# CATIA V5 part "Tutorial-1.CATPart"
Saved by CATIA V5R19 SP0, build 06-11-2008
Part number: c06_tut1
Bounding box of the stored display mesh (mm): x -101.839 to 0, y -66 to 66, z 0 to 106.23
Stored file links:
  D:\Shriniwas\v5_r19\Part files\c06\c06_tut1.CATPart
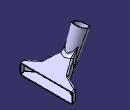
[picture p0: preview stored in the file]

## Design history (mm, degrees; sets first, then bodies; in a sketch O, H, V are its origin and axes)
Body1 (main body)
  Sketch1 on zx-plane, origin (0, 0, 0), H (-1, 0, 0), V (0, 0, 1)
    axis line L1 (0, 0) -> (178.0059, 0)
    line L2 (0, 0) -> (53.9276, 26.3023)
    line L3 (53.9276, 26.3023) -> (86.4666, 99.3859)
    point P3 (86.4666, 99.3859)
    angle L1 L2 = 26
    angle L2 L3 = 140
    length L3 = 80
    length L2 = 60
    horizontal: L1 H
  Sketch2 on yz-plane, origin (0, 0, 0), H (0, 1, 0), V (0, 0, 1)
    point P1 (79.721, 0)
    coincidence: P1 H
  Plane1 "Plane.1": type 3Points, Element1 Sketch2, Element2 Sketch1.O, Element3 vertex [element of Sketch1 | element of Sketch1]
  Sketch3 on Plane1, origin (0, 0, 0), H (0, -1, 0), V (-0.8988, 0, 0.4384)
    line L1 (0, 0) -> (-66, 0)
    point P1 (-66, 0)
    line L2 (-66, 0) -> (-65.4759, 10)
    point P2 (-65.4759, 10)
    line L3 (-65.4759, 10) -> (-33, 25)
    point P3 (-33, 25)
    line L4 (-33, 25) -> (-12.1773, 65)
    point P4 (-12.1773, 65)
    line L5 (-12.1773, 65) -> (0, 65)
    point P5 (0, 65)
    point P6 (65.4759, 10)
    point P7 (66, 0)
    line L6 (66, 0) -> (65.4759, 10)
    point P8 (33, 25)
    line L7 (65.4759, 10) -> (33, 25)
    point P9 (0, 0)
    line L8 (0, 0) -> (66, 0)
    point P10 (12.1773, 65)
    line L9 (33, 25) -> (12.1773, 65)
    point P11 (0, 65)
    line L10 (12.1773, 65) -> (0, 65)
    axis line L11 (66, 0) -> (66, 76.5877)
    angle L4 L9 = 55
    distance P3 P8 = 66
    distance P7 P1 = 132
    angle L11 L6 = 3
    distance P1 P2 V = 10
    distance L1 P3 = 25
    distance L5 L1 = 65
    horizontal: L1 H, L5 H
    coincidence: P5 V, O P9, P5 P11
    symmetry: P2 P6 V, P1 P7 V, L2 L6 V, P3 P8 V, L3 L7 V, O P9 V, L1 L8 V, P4 P10 V, L4 L9 V, P5 P11 V, L5 L10 V
    vertical: L11 V
  Pad1: profile Sketch3, direction along xy-plane, length 28
  Plane2 "Plane.2": type Normal, Curve Sketch1, RefPoint Sketch1.P3
  Sketch4 on Plane2, origin (-51.2336, 0, 115.0726), H (0, -1, 0), V (0.9135, 0, 0.4067)
    circle A1 centre (0, -38.5673) radius 17
    point P1 (0, -38.5673)
    reference projected point E1 (0, -38.5673) from Sketch1.P3
    radius A1 = 17
    coincidence: P1 E1
  Pad2: profile Sketch4, direction (0.4067, 0, -0.9135), length 0, opposite side up to Plane1
  Draft1: Angle 2, SupportToDraft face of Pad2 from Sketch4.A1, PullDir end face of Pad2, Neutral end face of Pad2
  Fillet1: radius 12, on edge [face of Pad2 from Sketch4.A1 | end face of Pad1]; edge [face of Pad2 from Sketch4.A1 | face of Pad1 from Sketch3.L4]; edge [face of Pad2 from Sketch4.A1 | face of Pad1 from Sketch3.L9]
  Fillet2: radius 3, on edge [face of Pad1 from Sketch3.L4 | end face of Pad1]; edge [end face of Pad1 | face of Pad1 from Sketch3.L3]; edge [face of Fillet1 | face of Fillet1]; edge [end face of Pad1 | face of Pad1 from Sketch3.L7]; edge [end face of Pad1 | face of Pad1 from Sketch3.L6]; edge [face of Pad1 from Sketch3.L7 | face of Pad1]; edge [end face of Pad1 | face of Pad1 from Sketch3.L2]; edge [face of Pad1 | face of Pad1 from Sketch3.L9]; edge [face of Pad1 from Sketch3.L3 | face of Pad1]; edge [face of Pad1 from Sketch3.L7 | face of Pad1 from Sketch3.L9]; edge [face of Pad1 from Sketch3.L4 | face of Pad1 from Sketch3.L3]; edge [face of Pad1 from Sketch3.L6 | face of Pad1]; edge [face of Pad1 from Sketch3.L6 | face of Pad1 from Sketch3.L7]; edge [face of Pad1 from Sketch3.L3 | face of Pad1 from Sketch3.L2]; edge [face of Pad1 from Sketch3.L2 | face of Pad1]
  Shell1: ExtOffset 0, IntOffset 2, Face (face of Pad1 from Sketch3.L1; end face of Pad2)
